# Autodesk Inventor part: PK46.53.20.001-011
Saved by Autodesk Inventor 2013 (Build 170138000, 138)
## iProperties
Created: 2005-03
Part Number: PK46.53.20.001-011
Material: Generic
Document SubType Name: Modeling
Designer: tedescj
Manufacturer: Standard
Standards Organization: Custom
Mass: 4751.84 g
Surface Area: 3132.04 cm^2
Volume: 604.56 cm^3
Density: 7.86 g/cm^3
Author: tedescj
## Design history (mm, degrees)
derived "PK46.53.20.001-01.ipt"
  sketch "Эскиз1"
    geometry: L1 (-264.331, 0)-(-690, 0) reference; L2 (-690, 0)-(-665.652, -65.629) reference; L3 (170, -646.916)-(240, -646.916) reference; L4 (240, -646.916)-(91.941, -247.826) reference; L5 (170, -646.916)-(32.608, -429.61) reference; L6 (-414.127, -118.858)-(-665.652, -65.629) reference; L7 (0, 0)-(-559.054, -803.691) reference; L8 (148.869, -401.272)-(144.181, -403.012) reference; L9 (137.737, -371.269)-(133.05, -373.008) reference; L10 (-89.677, -42.515)-(-91.976, -46.956) reference; L11 (-119.608, -28.638)-(-121.512, -33.261) reference; L12 (-89.677, -42.515)-(-104.341, -34.926) reference; L13 (-119.608, -28.638)-(-104.341, -34.926) reference; L14 (-103.508, -35.71)-(-103.28, -35.269) reference; L15 (143.908, -386.046)-(143.303, -386.271) reference; A1 r 380 centre (-264.331, -380) between (91.941, -247.826) and (-264.331, 0) reference; A2 r 25.5 centre (120, -394.916) between (144.181, -403.012) and (133.05, -373.008) reference; A3 r 25.5 centre (-115, -57.916) between (-91.976, -46.956) and (-121.512, -33.261) reference; A4 r 700 centre (-559.054, -803.691) between (32.608, -429.61) and (-414.127, -118.858) reference; 1 further point
feature "Solid1::PK46.53.20.001-01.ipt" dims "d0" = 10
tag "TaggingFeature1"
body "Solid1"
